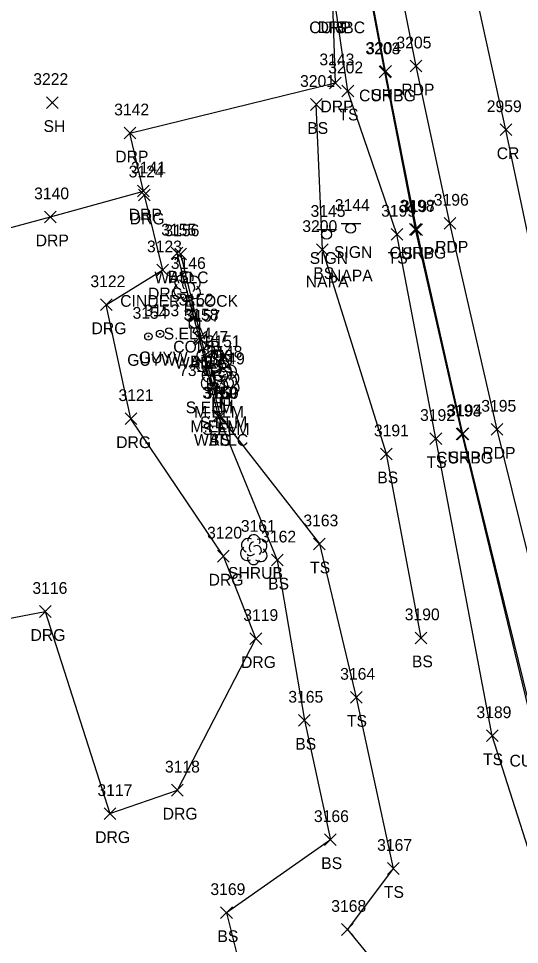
# Model space of a CAD drawing. Extents: x 1769141 to 1770911, y 735471 to 741449.
# Drawn here: x 1770416.3 to 1770501.6, y 737472.5 to 737630.1 of the extents above; entities that cross this region are included whole.
import ezdxf

# ---------------------------------------------------------------- set-up
doc = ezdxf.new("R2010")
doc.units = 0
for name, color, linetype in [('L_A', 7, 'Continuous'), ('L_C', 7, 'Continuous'), ('L_I', 7, 'Continuous'), ('L_TIC', 7, 'Continuous'), ('LELB', 7, 'Continuous'), ('LSH', 7, 'Continuous'), ('LTD', 7, 'Continuous'), ('LW', 7, 'Continuous'), ('P_A', 7, 'Continuous'), ('P_I', 7, 'Continuous'), ('P_TIC', 7, 'Continuous'), ('PET', 7, 'Continuous'), ('PRC', 7, 'Continuous'), ('PSP', 7, 'Continuous'), ('R_A', 7, 'Continuous'), ('R_I', 7, 'Continuous'), ('R_TIC', 7, 'Continuous'), ('RC', 7, 'Continuous'), ('RDG', 7, 'Continuous'), ('RDP', 7, 'Continuous'), ('S_A', 7, 'Continuous'), ('S_C', 7, 'Continuous'), ('S_I', 7, 'Continuous'), ('SSGN', 7, 'Continuous'), ('U_A', 7, 'Continuous'), ('U_C', 7, 'Continuous'), ('U_I', 7, 'Continuous'), ('UP', 7, 'Continuous'), ('UPGW', 7, 'Continuous')]:
    doc.layers.add(name, color=color, linetype=linetype)

msp = doc.modelspace()

# ---------------------------------------------------------------- linework, layer by layer
at = {"layer": 'L_TIC'}
for points in [[(1770471.38, 737616.75), (1770473.38, 737618.75)], [(1770473.38, 737616.75), (1770471.38, 737618.75)], [(1770421.09, 737614.78), (1770423.09, 737616.78)], [(1770423.09, 737614.78), (1770421.09, 737616.78)], [(1770466.02, 737614.45), (1770468.02, 737616.45)], [(1770468.02, 737614.45), (1770466.02, 737616.45)], [(1770479.75, 737592.37), (1770481.75, 737594.37)], [(1770481.75, 737592.37), (1770479.75, 737594.37)], [(1770442.3, 737589.16), (1770444.3, 737591.16)], [(1770444.3, 737589.16), (1770442.3, 737591.16)], [(1770467.06, 737589.76), (1770469.06, 737591.76)], [(1770469.06, 737589.76), (1770467.06, 737591.76)], [(1770442.91, 737589.04), (1770444.91, 737591.04)], [(1770444.91, 737589.04), (1770442.91, 737591.04)], [(1770446.1, 737574.72), (1770448.1, 737576.72)], [(1770448.1, 737574.72), (1770446.1, 737576.72)], [(1770446.4, 737574.52), (1770448.4, 737576.52)], [(1770448.4, 737574.52), (1770446.4, 737576.52)], [(1770449.31, 737561.43), (1770451.31, 737563.43)], [(1770451.31, 737561.43), (1770449.31, 737563.43)], [(1770449.67, 737561.39), (1770451.67, 737563.39)], [(1770451.67, 737561.39), (1770449.67, 737563.39)], [(1770449.67, 737561.39), (1770451.67, 737563.39)], [(1770451.67, 737561.39), (1770449.67, 737563.39)], [(1770486.37, 737557.62), (1770488.37, 737559.62)], [(1770488.37, 737557.62), (1770486.37, 737559.62)], [(1770477.94, 737555), (1770479.94, 737557)], [(1770479.94, 737555), (1770477.94, 737557)], [(1770466.55, 737539.69), (1770468.55, 737541.69)], [(1770468.55, 737539.69), (1770466.55, 737541.69)], [(1770459.37, 737536.94), (1770461.37, 737538.94)], [(1770461.37, 737536.94), (1770459.37, 737538.94)], [(1770483.85, 737523.71), (1770485.85, 737525.71)], [(1770485.85, 737523.71), (1770483.85, 737525.71)], [(1770472.82, 737513.59), (1770474.82, 737515.59)], [(1770474.82, 737513.59), (1770472.82, 737515.59)], [(1770463.99, 737509.69), (1770465.99, 737511.69)], [(1770465.99, 737509.69), (1770463.99, 737511.69)], [(1770495.98, 737507.06), (1770497.98, 737509.06)], [(1770497.98, 737507.06), (1770495.98, 737509.06)], [(1770468.41, 737489.38), (1770470.41, 737491.38)], [(1770470.41, 737489.38), (1770468.41, 737491.38)], [(1770479.11, 737484.48), (1770481.11, 737486.48)], [(1770481.11, 737484.48), (1770479.11, 737486.48)], [(1770450.73, 737476.96), (1770452.73, 737478.96)], [(1770452.73, 737476.96), (1770450.73, 737478.96)], [(1770471.3, 737474.1), (1770473.3, 737476.1)], [(1770473.3, 737474.1), (1770471.3, 737476.1)]]:
    msp.add_lwpolyline(points, dxfattribs=at)
at = {"layer": 'LELB'}
for points in [[(1770517.37, 737430.96), (1770506.98, 737476.62), (1770496.98, 737508.06), (1770487.37, 737558.62), (1770480.75, 737593.37), (1770472.38, 737617.75), (1770470.23, 737632.57)], [(1770484.85, 737524.71), (1770478.94, 737556), (1770468.06, 737590.76), (1770467.02, 737615.45)], [(1770443.3, 737590.16), (1770447.1, 737575.72), (1770450.31, 737562.43), (1770460.37, 737537.94), (1770464.99, 737510.69), (1770469.41, 737490.38), (1770451.73, 737477.96), (1770460.04, 737444.8), (1770476, 737422.35), (1770489.28, 737435.85), (1770480.09, 737452.37)], [(1770450.67, 737562.39), (1770467.55, 737540.69), (1770473.82, 737514.59), (1770480.11, 737485.48), (1770472.3, 737475.1), (1770488.45, 737455.36), (1770498.48, 737433.05), (1770487.64, 737420.51)]]:
    msp.add_lwpolyline(points, dxfattribs=at)
at = {"layer": 'LSH'}
msp.add_line((1770456.35, 737539.76), (1770456.35, 737539.76), dxfattribs=at)
msp.add_line((1770456.35, 737539.76), (1770456.35, 737539.76), dxfattribs=at)
msp.add_arc((1770456.39, 737541.19), 1.05, 335.5272, 180.9563, dxfattribs=at)
for centre, major_axis, ratio, start_param, end_param in [((1770455.55, 737540.42), (1.21, -0.51), 0.895232, 1.570796, 4.712389), ((1770456.14, 737540.22), (-0.208, -0.792), 0.645439, 3.141593, 6.283185), ((1770457.39, 737540.34), (-1.14, -0.48), 0.949671, 1.570796, 4.712389), ((1770455.26, 737539.05), (0.58, -1.04), 0.959034, 3.141593, 6.283185), ((1770456.85, 737539.59), (-0.5, 0.667), 0.989748, 3.141593, 6.283185), ((1770457.35, 737538.92), (-1.09, 0.79), 0.841452, 1.570796, 4.712389), ((1770456.35, 737538.26), (0.26, 1.06), 0.942809, 1.570796, 4.712389), ((1770455.89, 737539.01), (-0.625, -0.083), 0.423636, 0, 3.141593)]:
    msp.add_ellipse(centre, major_axis=major_axis, ratio=ratio, start_param=start_param, end_param=end_param, dxfattribs=at)
at = {"layer": 'LTD'}
for p, q in [((1770445, 737584.48), (1770445, 737584.48)), ((1770445, 737584.48), (1770445, 737584.48)), ((1770448.76, 737571.92), (1770448.76, 737571.92)), ((1770448.76, 737571.92), (1770448.76, 737571.92)), ((1770450.31, 737571.17), (1770450.31, 737571.17)), ((1770450.31, 737571.17), (1770450.31, 737571.17)), ((1770451.18, 737569.38), (1770451.18, 737569.38)), ((1770451.18, 737569.38), (1770451.18, 737569.38)), ((1770449.67, 737568.7), (1770449.67, 737568.7)), ((1770449.67, 737568.7), (1770449.67, 737568.7)), ((1770451.59, 737568.24), (1770451.59, 737568.24)), ((1770451.59, 737568.24), (1770451.59, 737568.24))]:
    msp.add_line(p, q, dxfattribs=at)
for centre in [(1770445.04, 737585.91), (1770448.81, 737573.36), (1770450.35, 737572.61), (1770449.72, 737570.13), (1770451.23, 737570.81), (1770451.64, 737569.67)]:
    msp.add_arc(centre, 1.05, 335.5272, 180.9563, dxfattribs=at)
for centre, major_axis, ratio, start_param, end_param in [((1770444.21, 737585.15), (1.21, -0.51), 0.895232, 1.570796, 4.712389), ((1770446.04, 737585.06), (-1.14, -0.48), 0.949671, 1.570796, 4.712389), ((1770444.79, 737584.94), (-0.208, -0.792), 0.645439, 3.141593, 6.283185), ((1770445.5, 737584.31), (-0.5, 0.667), 0.989748, 3.141593, 6.283185), ((1770443.91, 737583.77), (0.58, -1.04), 0.959034, 3.141593, 6.283185), ((1770444.54, 737583.73), (-0.625, -0.083), 0.423636, 0, 3.141593), ((1770446, 737583.65), (-1.09, 0.79), 0.841452, 1.570796, 4.712389), ((1770445, 737582.98), (0.26, 1.06), 0.942809, 1.570796, 4.712389), ((1770447.97, 737572.59), (1.21, -0.51), 0.895232, 1.570796, 4.712389), ((1770449.8, 737572.51), (-1.14, -0.48), 0.949671, 1.570796, 4.712389), ((1770447.68, 737571.21), (0.58, -1.04), 0.959034, 3.141593, 6.283185), ((1770448.55, 737572.38), (-0.208, -0.792), 0.645439, 3.141593, 6.283185), ((1770449.52, 737571.84), (1.21, -0.51), 0.895232, 1.570796, 4.712389), ((1770449.26, 737571.76), (-0.5, 0.667), 0.989748, 3.141593, 6.283185), ((1770450.1, 737571.63), (-0.208, -0.792), 0.645439, 3.141593, 6.283185), ((1770451.35, 737571.76), (-1.14, -0.48), 0.949671, 1.570796, 4.712389), ((1770448.88, 737569.37), (1.21, -0.51), 0.895232, 1.570796, 4.712389), ((1770448.76, 737570.42), (0.26, 1.06), 0.942809, 1.570796, 4.712389), ((1770448.3, 737571.17), (-0.625, -0.083), 0.423636, 0, 3.141593), ((1770449.22, 737570.47), (0.58, -1.04), 0.959034, 3.141593, 6.283185), ((1770450.39, 737570.04), (1.21, -0.51), 0.895232, 1.570796, 4.712389), ((1770449.76, 737571.09), (-1.09, 0.79), 0.841452, 1.570796, 4.712389), ((1770450.81, 737571.01), (-0.5, 0.667), 0.989748, 3.141593, 6.283185), ((1770450.98, 737569.84), (-0.208, -0.792), 0.645439, 3.141593, 6.283185), ((1770451.31, 737570.34), (-1.09, 0.79), 0.841452, 1.570796, 4.712389), ((1770452.23, 737569.96), (-1.14, -0.48), 0.949671, 1.570796, 4.712389), ((1770450.1, 737568.67), (0.58, -1.04), 0.959034, 3.141593, 6.283185), ((1770449.47, 737569.16), (-0.208, -0.792), 0.645439, 3.141593, 6.283185), ((1770450.31, 737569.67), (0.26, 1.06), 0.942809, 1.570796, 4.712389), ((1770449.85, 737570.42), (-0.625, -0.083), 0.423636, 0, 3.141593), ((1770450.8, 737568.9), (1.21, -0.51), 0.895232, 1.570796, 4.712389), ((1770450.17, 737568.53), (-0.5, 0.667), 0.989748, 3.141593, 6.283185), ((1770450.72, 737569.28), (-1.14, -0.48), 0.949671, 1.570796, 4.712389), ((1770451.38, 737568.69), (-0.208, -0.792), 0.645439, 3.141593, 6.283185), ((1770451.68, 737569.21), (-0.5, 0.667), 0.989748, 3.141593, 6.283185), ((1770452.18, 737568.54), (-1.09, 0.79), 0.841452, 1.570796, 4.712389), ((1770452.63, 737568.82), (-1.14, -0.48), 0.949671, 1.570796, 4.712389), ((1770448.59, 737567.99), (0.58, -1.04), 0.959034, 3.141593, 6.283185), ((1770449.22, 737567.95), (-0.625, -0.083), 0.423636, 0, 3.141593), ((1770450.51, 737567.53), (0.58, -1.04), 0.959034, 3.141593, 6.283185), ((1770450.67, 737567.87), (-1.09, 0.79), 0.841452, 1.570796, 4.712389), ((1770451.18, 737567.88), (0.26, 1.06), 0.942809, 1.570796, 4.712389), ((1770450.73, 737568.63), (-0.625, -0.083), 0.423636, 0, 3.141593), ((1770451.13, 737567.49), (-0.625, -0.083), 0.423636, 0, 3.141593), ((1770452.09, 737568.07), (-0.5, 0.667), 0.989748, 3.141593, 6.283185), ((1770452.59, 737567.4), (-1.09, 0.79), 0.841452, 1.570796, 4.712389), ((1770449.67, 737567.2), (0.26, 1.06), 0.942809, 1.570796, 4.712389), ((1770451.59, 737566.74), (0.26, 1.06), 0.942809, 1.570796, 4.712389)]:
    msp.add_ellipse(centre, major_axis=major_axis, ratio=ratio, start_param=start_param, end_param=end_param, dxfattribs=at)
at = {"layer": 'LW'}
msp.add_lwpolyline([(1770443.91, 737590.04), (1770447.4, 737575.52), (1770450.67, 737562.39)], dxfattribs=at)
at = {"layer": 'P_TIC'}
for points in [[(1770483, 737621), (1770485, 737623)], [(1770485, 737621), (1770483, 737623)], [(1770477.82, 737620.08), (1770479.82, 737622.08)], [(1770479.82, 737620.08), (1770477.82, 737622.08)], [(1770498.3, 737610.16), (1770500.3, 737612.16)], [(1770500.3, 737610.16), (1770498.3, 737612.16)], [(1770488.76, 737594.24), (1770490.76, 737596.24)], [(1770490.76, 737594.24), (1770488.76, 737596.24)], [(1770483.11, 737593.15), (1770485.11, 737595.15)], [(1770485.11, 737593.15), (1770483.11, 737595.15)], [(1770496.79, 737559.19), (1770498.79, 737561.19)], [(1770498.79, 737559.19), (1770496.79, 737561.19)], [(1770490.98, 737558.42), (1770492.98, 737560.42)], [(1770492.98, 737558.42), (1770490.98, 737560.42)]]:
    msp.add_lwpolyline(points, dxfattribs=at)
at = {"layer": 'PET'}
msp.add_lwpolyline([(1770592.49, 737245.88), (1770581.45, 737278.47), (1770564.99, 737326.7), (1770540.85, 737402.85), (1770531.81, 737432.59), (1770518.16, 737480.64), (1770510.53, 737508.77), (1770497.79, 737560.19), (1770489.76, 737595.24), (1770484, 737622), (1770479.29, 737645.74), (1770471.87, 737685.43), (1770468.18, 737707.71), (1770464.57, 737732.3), (1770461.1, 737760.5), (1770457.07, 737800.74), (1770455.08, 737840.17)], dxfattribs=at)
at = {"layer": 'PRC'}
msp.add_lwpolyline([(1770611.43, 737227.28), (1770596.59, 737271.46), (1770580.67, 737318.49), (1770564.59, 737367.31), (1770551.93, 737407.86), (1770542.43, 737439.84), (1770534.51, 737467.45), (1770524.2, 737503.43), (1770508.76, 737566.26), (1770499.3, 737611.16), (1770490.31, 737651.95), (1770482.16, 737697.06), (1770472.91, 737762.84), (1770468.76, 737807.58), (1770466.84, 737850.58)], dxfattribs=at)
at = {"layer": 'PSP'}
msp.add_lwpolyline([(1770587.45, 737244.33), (1770575.08, 737276.15), (1770567.84, 737299.32), (1770558.98, 737324.95), (1770547.16, 737358.66), (1770533.81, 737401.32), (1770525.74, 737428.65), (1770525.14, 737430.69), (1770512.34, 737478.31), (1770504.59, 737507.96), (1770491.98, 737559.42), (1770484.11, 737594.15), (1770478.82, 737621.08), (1770474.55, 737643.98), (1770465.86, 737686.48), (1770463.19, 737706.94), (1770459.77, 737731.62), (1770456.5, 737760.12), (1770452.89, 737800.45), (1770450.15, 737840.19)], dxfattribs=at)
at = {"layer": 'R_TIC'}
for points in [[(1770477.71, 737619.99), (1770479.71, 737621.99)], [(1770479.71, 737619.99), (1770477.71, 737621.99)], [(1770469.24, 737618.12), (1770471.24, 737620.12)], [(1770471.24, 737618.12), (1770469.24, 737620.12)], [(1770434.3, 737609.6), (1770436.3, 737611.6)], [(1770436.3, 737609.6), (1770434.3, 737611.6)], [(1770436.59, 737599.72), (1770438.59, 737601.72)], [(1770438.59, 737599.72), (1770436.59, 737601.72)], [(1770436.76, 737599.05), (1770438.76, 737601.05)], [(1770438.76, 737599.05), (1770436.76, 737601.05)], [(1770420.76, 737595.33), (1770422.76, 737597.33)], [(1770422.76, 737595.33), (1770420.76, 737597.33)], [(1770482.89, 737593.23), (1770484.89, 737595.23)], [(1770484.89, 737593.23), (1770482.89, 737595.23)], [(1770439.88, 737586.3), (1770441.88, 737588.3)], [(1770441.88, 737586.3), (1770439.88, 737588.3)], [(1770430.26, 737580.38), (1770432.26, 737582.38)], [(1770432.26, 737580.38), (1770430.26, 737582.38)], [(1770434.46, 737561), (1770436.46, 737563)], [(1770436.46, 737561), (1770434.46, 737563)], [(1770490.84, 737558.38), (1770492.84, 737560.38)], [(1770492.84, 737558.38), (1770490.84, 737560.38)], [(1770450.2, 737537.61), (1770452.2, 737539.61)], [(1770452.2, 737537.61), (1770450.2, 737539.61)], [(1770419.87, 737528.2), (1770421.87, 737530.2)], [(1770421.87, 737528.2), (1770419.87, 737530.2)], [(1770455.72, 737523.59), (1770457.72, 737525.59)], [(1770457.72, 737523.59), (1770455.72, 737525.59)], [(1770442.38, 737497.8), (1770444.38, 737499.8)], [(1770444.38, 737497.8), (1770442.38, 737499.8)], [(1770430.88, 737493.81), (1770432.88, 737495.81)], [(1770432.88, 737493.81), (1770430.88, 737495.81)]]:
    msp.add_lwpolyline(points, dxfattribs=at)
at = {"layer": 'RC'}
msp.add_lwpolyline([(1770504.33, 737507.82), (1770491.84, 737559.38), (1770483.89, 737594.23), (1770478.71, 737620.99), (1770474.61, 737642.8)], dxfattribs=at)
at = {"layer": 'RDG'}
msp.add_lwpolyline([(1770404.16, 737526.02), (1770420.87, 737529.2), (1770431.88, 737494.81), (1770443.38, 737498.8), (1770456.72, 737524.59), (1770451.2, 737538.61), (1770435.46, 737562), (1770431.26, 737581.38), (1770440.88, 737587.3), (1770437.76, 737600.05)], dxfattribs=at)
at = {"layer": 'RDP'}
for points in [[(1770469.75, 737632.6), (1770470.24, 737619.12)], [(1770406.79, 737592.33), (1770421.76, 737596.33), (1770437.59, 737600.72), (1770435.3, 737610.6), (1770470.24, 737619.12)]]:
    msp.add_lwpolyline(points, dxfattribs=at)
at = {"layer": 'SSGN'}
for p, q in [((1770471.24, 737595.2), (1770474.57, 737595.2)), ((1770472.88, 737594.37), (1770472.88, 737594.37)), ((1770467.11, 737594.19), (1770470.44, 737594.19)), ((1770468.76, 737593.36), (1770468.76, 737593.36))]:
    msp.add_line(p, q, dxfattribs=at)
for centre in [(1770472.88, 737594.37), (1770468.76, 737593.36)]:
    msp.add_circle(centre, 0.833, dxfattribs=at)
at = {"layer": 'UP'}
for p, q in [((1770445.44, 737577.43), (1770445.44, 737579.09)), ((1770445.44, 737579.09), (1770447.11, 737579.09)), ((1770446.53, 737579.93), (1770446.28, 737579.09)), ((1770447.11, 737579.09), (1770447.11, 737577.43)), ((1770447.11, 737577.43), (1770445.44, 737577.43)), ((1770446.03, 737576.59), (1770446.28, 737577.43)), ((1770446.28, 737578.26), (1770446.28, 737578.26))]:
    msp.add_line(p, q, dxfattribs=at)
msp.add_circle((1770446.28, 737578.26), 0.833, dxfattribs=at)
at = {"layer": 'UPGW'}
for centre, radius in [((1770440.41, 737576.43), 0.625), ((1770438.43, 737576), 0.625), ((1770438.43, 737576), 0.0833), ((1770440.41, 737576.43), 0.0833)]:
    msp.add_circle(centre, radius, dxfattribs=at)

# ---------------------------------------------------------------- texts
at = {"layer": 'L_A'}
for s, p in [('TS', (1770468.64, 737627.57)), ('TS', (1770470.79, 737612.75)), ('SH', (1770420.58, 737610.78)), ('BS', (1770465.47, 737610.45)), ('TS', (1770479.16, 737588.37)), ('WALLC', (1770439.45, 737585.04)), ('BS', (1770441.74, 737585.16)), ('BS', (1770466.5, 737585.76)), ('H', (1770444.43, 737579.48)), ('WALLC', (1770442.93, 737570.52)), ('BS', (1770445.54, 737570.72)), ('H', (1770448.19, 737566.92)), ('H', (1770449.74, 737566.17)), ('H', (1770450.62, 737564.38)), ('H', (1770449.11, 737563.7)), ('H', (1770451.03, 737563.24)), ('WALLC', (1770446.2, 737557.39)), ('BS', (1770448.75, 737557.43)), ('TS', (1770449.08, 737557.39)), ('TS', (1770485.78, 737553.62)), ('BS', (1770477.39, 737551)), ('TS', (1770465.96, 737535.69)), ('SHRUB', (1770451.98, 737534.76)), ('BS', (1770458.81, 737532.94)), ('BS', (1770483.29, 737519.71)), ('TS', (1770472.23, 737509.59)), ('BS', (1770463.43, 737505.69)), ('TS', (1770495.39, 737503.06)), ('BS', (1770467.85, 737485.38)), ('TS', (1770478.52, 737480.48)), ('BS', (1770450.18, 737472.96))]:
    msp.add_text(s, height=2, dxfattribs=at).set_placement(p)
at = {"layer": 'L_C'}
for s, p in [('CINDER BLOCK', (1770433.63, 737581.04)), ('S.ELM', (1770441.03, 737575.48)), ('S.ELM', (1770444.79, 737562.92)), ('M.ELM', (1770446.21, 737562.17)), ('M.ELM', (1770445.58, 737559.7)), ('S.ELM', (1770447.22, 737560.38)), ('S.ELM', (1770447.62, 737559.24))]:
    msp.add_text(s, height=2, dxfattribs=at).set_placement(p)
at = {"layer": 'L_I'}
for s, p in [('3202', (1770469.04, 737620.75)), ('3222', (1770418.83, 737618.78)), ('3201', (1770464.25, 737618.45)), ('3199', (1770478.05, 737596.37)), ('3155', (1770440.61, 737593.16)), ('3156', (1770441.16, 737593.04)), ('3200', (1770464.63, 737593.76)), ('3146', (1770442.25, 737587.48)), ('3158', (1770444.41, 737578.72)), ('3157', (1770444.71, 737578.52)), ('3147', (1770446.07, 737574.92)), ('3151', (1770448.18, 737574.17)), ('3148', (1770448.49, 737572.38)), ('3150', (1770446.89, 737571.7)), ('3149', (1770448.89, 737571.24)), ('3159', (1770447.61, 737565.43)), ('3160', (1770447.84, 737565.39)), ('3160', (1770447.84, 737565.39)), ('3192', (1770484.68, 737561.62)), ('3191', (1770476.82, 737559)), ('3163', (1770464.81, 737543.69)), ('3161', (1770454.17, 737542.76)), ('3162', (1770457.63, 737540.94)), ('3190', (1770482.07, 737527.71)), ('3164', (1770471.08, 737517.59)), ('3165', (1770462.25, 737513.69)), ('3189', (1770494.28, 737511.06)), ('3166', (1770466.61, 737493.38)), ('3167', (1770477.37, 737488.48)), ('3169', (1770448.99, 737480.96)), ('3168', (1770469.56, 737478.1))]:
    msp.add_text(s, height=2, dxfattribs=at).set_placement(p)
at = {"layer": 'P_A'}
for s, p in [('SHP', (1770476.36, 737616.08)), ('RDP', (1770481.48, 737617)), ('CR', (1770497.73, 737606.16)), ('SHP', (1770481.64, 737589.15)), ('RDP', (1770487.25, 737590.24)), ('RDP', (1770495.28, 737555.19)), ('SHP', (1770489.52, 737554.42))]:
    msp.add_text(s, height=2, dxfattribs=at).set_placement(p)
at = {"layer": 'P_I'}
for s, p in [('3204', (1770475.49, 737624.08)), ('3205', (1770480.66, 737625)), ('2959', (1770496.03, 737614.16)), ('3197', (1770481.42, 737597.15)), ('3196', (1770487.02, 737598.24)), ('3194', (1770489.29, 737562.42)), ('3195', (1770495.1, 737563.19))]:
    msp.add_text(s, height=2, dxfattribs=at).set_placement(p)
at = {"layer": 'R_A'}
for s, p in [('CURBC', (1770465.81, 737627.57)), ('DRP', (1770467.24, 737627.6)), ('CURBG', (1770474.29, 737615.99)), ('DRP', (1770467.72, 737614.12)), ('DRP', (1770432.79, 737605.6)), ('DRP', (1770435.08, 737595.72)), ('DRG', (1770435.25, 737595.05)), ('DRP', (1770419.25, 737591.33)), ('CURBG', (1770479.47, 737589.23)), ('DRG', (1770438.37, 737582.3)), ('DRG', (1770428.75, 737576.38)), ('DRG', (1770432.95, 737557)), ('CURBG', (1770487.43, 737554.38)), ('DRG', (1770448.68, 737533.61)), ('DRG', (1770418.36, 737524.2)), ('DRG', (1770454.2, 737519.59)), ('CURBC', (1770499.91, 737502.82)), ('CURBG', (1770499.91, 737502.82)), ('DRG', (1770440.87, 737493.8)), ('DRG', (1770429.37, 737489.81))]:
    msp.add_text(s, height=2, dxfattribs=at).set_placement(p)
at = {"layer": 'R_I'}
for s, p in [('3203', (1770475.37, 737623.99)), ('3143', (1770467.54, 737622.12)), ('3142', (1770432.61, 737613.6)), ('3141', (1770435.47, 737603.72)), ('3124', (1770435.07, 737603.05)), ('3140', (1770418.98, 737599.33)), ('3198', (1770481.2, 737597.23)), ('3123', (1770438.19, 737590.3)), ('3122', (1770428.56, 737584.38)), ('3121', (1770433.34, 737565)), ('3193', (1770489.15, 737562.38)), ('3120', (1770448.42, 737541.61)), ('3116', (1770418.69, 737532.2)), ('3119', (1770454.58, 737527.59)), ('3118', (1770441.25, 737501.8)), ('3117', (1770429.76, 737497.81))]:
    msp.add_text(s, height=2, dxfattribs=at).set_placement(p)
at = {"layer": 'S_A'}
for p in [(1770470.02, 737589.35), (1770465.89, 737588.34)]:
    msp.add_text('SIGN', height=2, dxfattribs=at).set_placement(p)
at = {"layer": 'S_C'}
for p in [(1770469.34, 737585.35), (1770465.22, 737584.34)]:
    msp.add_text('NAPA', height=2, dxfattribs=at).set_placement(p)
at = {"layer": 'S_I'}
for s, p in [('3144', (1770470.17, 737597.35)), ('3145', (1770466.04, 737596.34))]:
    msp.add_text(s, height=2, dxfattribs=at).set_placement(p)
at = {"layer": 'U_A'}
for s, p in [('COMB', (1770442.66, 737573.26)), ('GUYW', (1770434.83, 737571)), ('GUYW', (1770436.81, 737571.43))]:
    msp.add_text(s, height=2, dxfattribs=at).set_placement(p)
at = {"layer": 'U_C'}
msp.add_text('73-1', height=2, dxfattribs=at).set_placement((1770443.66, 737569.26))
at = {"layer": 'U_I'}
for s, p in [('3152', (1770443.59, 737581.26)), ('3154', (1770435.74, 737579)), ('3153', (1770437.72, 737579.43))]:
    msp.add_text(s, height=2, dxfattribs=at).set_placement(p)

doc.saveas('drawing.dxf')
